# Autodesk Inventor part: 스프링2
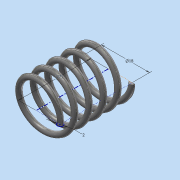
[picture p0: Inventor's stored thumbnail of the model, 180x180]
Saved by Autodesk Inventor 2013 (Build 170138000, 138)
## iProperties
Created: 2016-10
Part Number: 스프링2
Material: 강철, 탄소
Document SubType Name: Modeling
Designer: user
Mass: 6.88075 g
Surface Area: 17.7314 cm^2
Volume: 0.874302 cm^3
Density: 7.87 g/cm^3
Author: user
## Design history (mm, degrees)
sketch "스케치1"
  geometry: L1 (0, 0)-(9, 0); L2 (9, 0)-(9, 27); L3 (9, 27)-(0, 27); L4 (0, 27)-(0, 0); C1 r 1 at (9, 0)
  constraints: 8 end point, 2 parallel, 1 centre point, 1 coincident, 1 horizontal, 1 perpendicular
  dimensions: "d0" = 27 distance of L3.end L1.start (derived); "d1" = 18 diameter of L2 L4; "d2" = 2 diameter of C1
feature "코일1" pitch "d3" = 10; turns "d5" = 5; dims "d4" = 27 (= d0), "d6" = 0, angle "d7" = 90 deg, angle "d8" = 90 deg, "d9" = 0, "d10" = 0
sketch "스케치2"
  geometry: L1 (-8, 0)-(-10, 0) reference; 1 further point
  constraints: 1 horizontal alignment
extrude "돌출1" cut sketch "스케치2" distance "d11" = 10; taper "d12" = 0 deg
node "작업 평면1"
sketch "스케치3"
  geometry: L1 (-1, 0)-(1, 0) reference; 1 further point
  constraints: 1 horizontal alignment
extrude "돌출2" cut sketch "스케치3" distance "d14" = 10; taper "d15" = 0 deg
node "솔리드1"
node "절단 모서리 투영1"
node "절단 모서리 투영2"
other parameters: "d13" = 0
